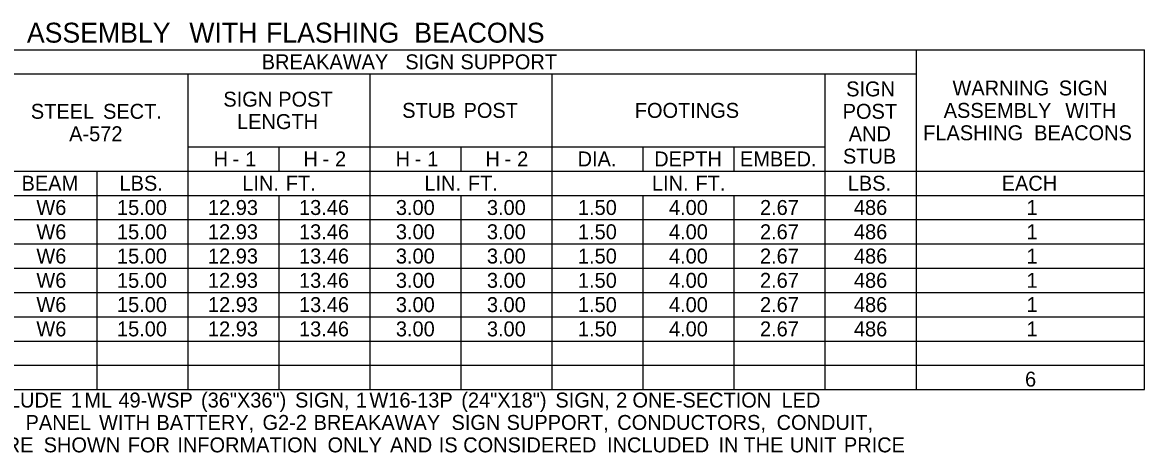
# Model space of a CAD drawing. Extents: x 229 to 4210, y 35 to 1715.
# Drawn here: x 2842.4 to 3293.1, y 377.4 to 550.1 of the extents above; entities that cross this region are included whole.
import ezdxf

# ---------------------------------------------------------------- set-up
doc = ezdxf.new("R2010")
doc.units = 0
doc.layers.add('Default', color=7, linetype='Continuous')

msp = doc.modelspace()

# ---------------------------------------------------------------- linework, layer by layer
at = {"layer": 'Default'}
for p, q in [((2519.95, 539.2), (3293.13, 539.2)), ((3201.48, 402.7), (3201.48, 539.2)), ((3293.13, 402.7), (3293.13, 539.2)), ((3293.13, 402.7), (3293.13, 539.2)), ((2795.88, 529.45), (3201.48, 529.45)), ((2908.98, 402.7), (2908.98, 529.45)), ((2982.1, 500.2), (2982.1, 529.45)), ((2982.1, 402.7), (2982.1, 529.45)), ((3055.23, 500.2), (3055.23, 529.45)), ((3055.23, 402.7), (3055.23, 529.45)), ((3164.91, 529.45), (3201.48, 529.45)), ((3164.91, 402.7), (3164.91, 529.45)), ((2908.98, 500.2), (3164.91, 500.2)), ((2945.54, 490.45), (2945.54, 500.2)), ((3018.66, 490.45), (3018.66, 500.2)), ((3091.79, 490.45), (3091.79, 500.2)), ((3128.35, 490.45), (3128.35, 500.2)), ((2795.88, 490.45), (3164.91, 490.45)), ((2872.41, 402.7), (2872.41, 490.45)), ((2908.98, 490.45), (2945.54, 490.45)), ((2945.54, 490.45), (2982.1, 490.45)), ((2982.1, 490.45), (3018.66, 490.45)), ((2982.1, 412.45), (2982.1, 490.45)), ((3018.66, 490.45), (3164.91, 490.45)), ((3055.23, 412.45), (3055.23, 490.45)), ((3164.91, 490.45), (3293.13, 490.45)), ((3164.91, 490.45), (3201.48, 490.45)), ((2519.95, 480.7), (3293.13, 480.7)), ((2872.41, 412.45), (2872.41, 480.7)), ((2908.98, 412.45), (2908.98, 480.7)), ((2945.54, 412.45), (2945.54, 480.7)), ((2945.54, 402.7), (2945.54, 480.7)), ((3018.66, 412.45), (3018.66, 480.7)), ((3018.66, 402.7), (3018.66, 480.7)), ((3091.79, 412.45), (3091.79, 480.7)), ((3091.79, 402.7), (3091.79, 480.7)), ((3128.35, 412.45), (3128.35, 480.7)), ((3128.35, 402.7), (3128.35, 480.7)), ((3164.91, 412.45), (3164.91, 480.7)), ((2519.95, 470.95), (3293.13, 470.95)), ((2519.95, 461.2), (3293.13, 461.2)), ((2519.95, 451.45), (3293.13, 451.45)), ((2519.95, 441.7), (3293.13, 441.7)), ((2519.95, 431.95), (3293.13, 431.95)), ((2519.95, 422.2), (3293.13, 422.2)), ((2519.95, 412.45), (3293.13, 412.45)), ((2519.95, 412.45), (3293.13, 412.45)), ((2519.95, 402.7), (3293.13, 402.7))]:
    msp.add_line(p, q, dxfattribs=at)

# ---------------------------------------------------------------- texts
for s, height, p in [(' ASSEMBLY', 8, (2841.26, 542.03)), (' WITH', 8, (2906.5, 542.03)), (' FLASHING', 8, (2937.3, 542.03)), (' BEACONS', 8, (2996.86, 542.03)), ('BREAKAWAY', 6, (2938.54, 531.33)), (' SIGN', 6, (2993.98, 531.33)), (' SUPPORT', 6, (3016.13, 531.33)), ('SIGN', 6, (3173.28, 520.45)), ('WARNING', 6, (3215.99, 520.83)), (' SIGN', 6, (3256.46, 520.83)), ('SIGN', 6, (2923.13, 516.33)), (' POST', 6, (2942.96, 516.33)), ('STEEL', 6, (2845.81, 511.45)), (' SECT.', 6, (2872.58, 511.45)), ('STUB', 6, (2994.96, 511.83)), (' POST', 6, (3017.38, 511.83)), ('FOOTINGS', 6, (3088.38, 511.83)), ('POST', 6, (3171.87, 511.45)), ('ASSEMBLY', 6, (3212.45, 511.83)), (' WITH', 6, (3259.05, 511.83)), ('LENGTH', 6, (2928.63, 507.33)), ('A-572', 6, (2861.21, 502.45)), ('AND', 6, (3174.32, 502.45)), ('FLASHING', 6, (3204.21, 502.83)), (' BEACONS', 6, (3246.55, 502.83)), ('H', 6, (2919.21, 492.33)), (' 1', 6, (2929.68, 492.33)), ('H', 6, (2955.3, 492.33)), (' 2', 6, (2965.77, 492.33)), ('H', 6, (2992.33, 492.33)), (' 1', 6, (3002.8, 492.33)), ('H', 6, (3028.43, 492.33)), (' 2', 6, (3038.89, 492.33)), ('DIA.', 6, (3065.41, 492.33)), ('DEPTH', 6, (3096.18, 492.33)), ('EMBED.', 6, (3130.62, 492.33)), ('STUB', 6, (3171.99, 493.45)), (' -', 6, (2924.62, 492.33)), (' -', 6, (2960.71, 492.33)), (' -', 6, (2997.74, 492.33)), (' -', 6, (3033.84, 492.33)), ('BEAM', 6, (2842.09, 482.58)), ('LBS.', 6, (2881.43, 482.58)), ('LIN.', 6, (2930.75, 482.58)), (' FT.', 6, (2946, 482.58)), ('LIN.', 6, (3003.87, 482.58)), (' FT.', 6, (3019.13, 482.58)), ('LIN.', 6, (3095.28, 482.58)), (' FT.', 6, (3110.54, 482.58)), ('LBS.', 6, (3173.93, 482.58)), ('EACH', 6, (3235.74, 482.58)), ('W6', 6, (2848.04, 472.83)), ('15.00', 6, (2880.41, 472.83)), ('12.93', 6, (2916.96, 472.83)), ('13.46', 6, (2953.52, 472.83)), ('3.00', 6, (2992.43, 472.83)), ('3.00', 6, (3028.99, 472.83)), ('1.50', 6, (3065.55, 472.83)), ('4.00', 6, (3102.12, 472.83)), ('2.67', 6, (3138.67, 472.83)), ('486', 6, (3176.39, 472.83)), ('1', 6, (3245.74, 472.83)), ('W6', 6, (2848.04, 463.08)), ('15.00', 6, (2880.41, 463.08)), ('12.93', 6, (2916.96, 463.08)), ('13.46', 6, (2953.52, 463.08)), ('3.00', 6, (2992.43, 463.08)), ('3.00', 6, (3028.99, 463.08)), ('1.50', 6, (3065.55, 463.08)), ('4.00', 6, (3102.12, 463.08)), ('2.67', 6, (3138.67, 463.08)), ('486', 6, (3176.39, 463.08)), ('1', 6, (3245.74, 463.08)), ('W6', 6, (2848.04, 453.33)), ('15.00', 6, (2880.41, 453.33)), ('12.93', 6, (2916.96, 453.33)), ('13.46', 6, (2953.52, 453.33)), ('3.00', 6, (2992.43, 453.33)), ('3.00', 6, (3028.99, 453.33)), ('1.50', 6, (3065.55, 453.33)), ('4.00', 6, (3102.12, 453.33)), ('2.67', 6, (3138.67, 453.33)), ('486', 6, (3176.39, 453.33)), ('1', 6, (3245.74, 453.33)), ('W6', 6, (2848.04, 443.58)), ('15.00', 6, (2880.41, 443.58)), ('12.93', 6, (2916.96, 443.58)), ('13.46', 6, (2953.52, 443.58)), ('3.00', 6, (2992.43, 443.58)), ('3.00', 6, (3028.99, 443.58)), ('1.50', 6, (3065.55, 443.58)), ('4.00', 6, (3102.12, 443.58)), ('2.67', 6, (3138.67, 443.58)), ('486', 6, (3176.39, 443.58)), ('1', 6, (3245.74, 443.58)), ('W6', 6, (2848.04, 433.83)), ('15.00', 6, (2880.41, 433.83)), ('12.93', 6, (2916.96, 433.83)), ('13.46', 6, (2953.52, 433.83)), ('3.00', 6, (2992.43, 433.83)), ('3.00', 6, (3028.99, 433.83)), ('1.50', 6, (3065.55, 433.83)), ('4.00', 6, (3102.12, 433.83)), ('2.67', 6, (3138.67, 433.83)), ('486', 6, (3176.39, 433.83)), ('1', 6, (3245.74, 433.83)), ('W6', 6, (2848.04, 424.08)), ('15.00', 6, (2880.41, 424.08)), ('12.93', 6, (2916.96, 424.08)), ('13.46', 6, (2953.52, 424.08)), ('3.00', 6, (2992.43, 424.08)), ('3.00', 6, (3028.99, 424.08)), ('1.50', 6, (3065.55, 424.08)), ('4.00', 6, (3102.12, 424.08)), ('2.67', 6, (3138.67, 424.08)), ('486', 6, (3176.39, 424.08)), ('1', 6, (3245.74, 424.08)), ('6', 6, (3245.12, 403.9)), (' INCLUDE', 6, (2820.96, 395.5)), (' 1', 6, (2859.64, 395.5)), (' ML', 6, (2865.09, 395.5)), (' 49-WSP', 6, (2878.76, 395.5)), (' (36"X36")', 6, (2911.93, 395.5)), (' SIGN,', 6, (2949.72, 395.5)), (' 1', 6, (2974.13, 395.5)), (' W16-13P', 6, (2979.58, 395.5)), (' (24"X18")', 6, (3016.47, 395.5)), (' SIGN,', 6, (3054.27, 395.5)), (' 2', 6, (3078.67, 395.5)), (' ONE-SECTION', 6, (3085.22, 395.5)), (' LED', 6, (3145.09, 395.5)), (' PANEL', 6, (2841.46, 386.5)), (' WITH', 6, (2870.98, 386.5)), (' BATTERY,', 6, (2894.05, 386.5)), (' G2-2', 6, (2936.63, 386.5)), (' BREAKAWAY', 6, (2957.15, 386.5)), (' SIGN', 6, (3012.53, 386.5)), (' SUPPORT,', 6, (3034.67, 386.5)), (' CONDUCTORS,', 6, (3079.11, 386.5)), (' CONDUIT,', 6, (3143.11, 386.5)), (' STRUCTURE', 6, (2795.16, 377.5)), (' SHOWN', 6, (2848.74, 377.5)), (' FOR', 6, (2882.52, 377.5)), (' INFORMATION', 6, (2902.43, 377.5)), (' ONLY', 6, (2962.76, 377.5)), (' AND', 6, (2987.85, 377.5)), (' IS', 6, (3007.43, 377.5)), (' CONSIDERED', 6, (3017.24, 377.5)), (' INCLUDED', 6, (3075.02, 377.5)), (' IN', 6, (3119.76, 377.5)), (' THE', 6, (3129.78, 377.5)), (' UNIT', 6, (3148.43, 377.5)), (' PRICE', 6, (3170.15, 377.5))]:
    msp.add_text(s, height=height, dxfattribs=at).set_placement(p)

doc.saveas('drawing.dxf')
